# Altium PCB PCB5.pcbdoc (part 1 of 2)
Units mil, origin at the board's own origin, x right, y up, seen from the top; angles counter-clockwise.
Board outline 5683.34 x 2704.79 mil, 4 copper layers (Top Layer, Inner1, Inner2, Bottom Layer); 104 components, 86 nets, 284 pads, 113 vias.
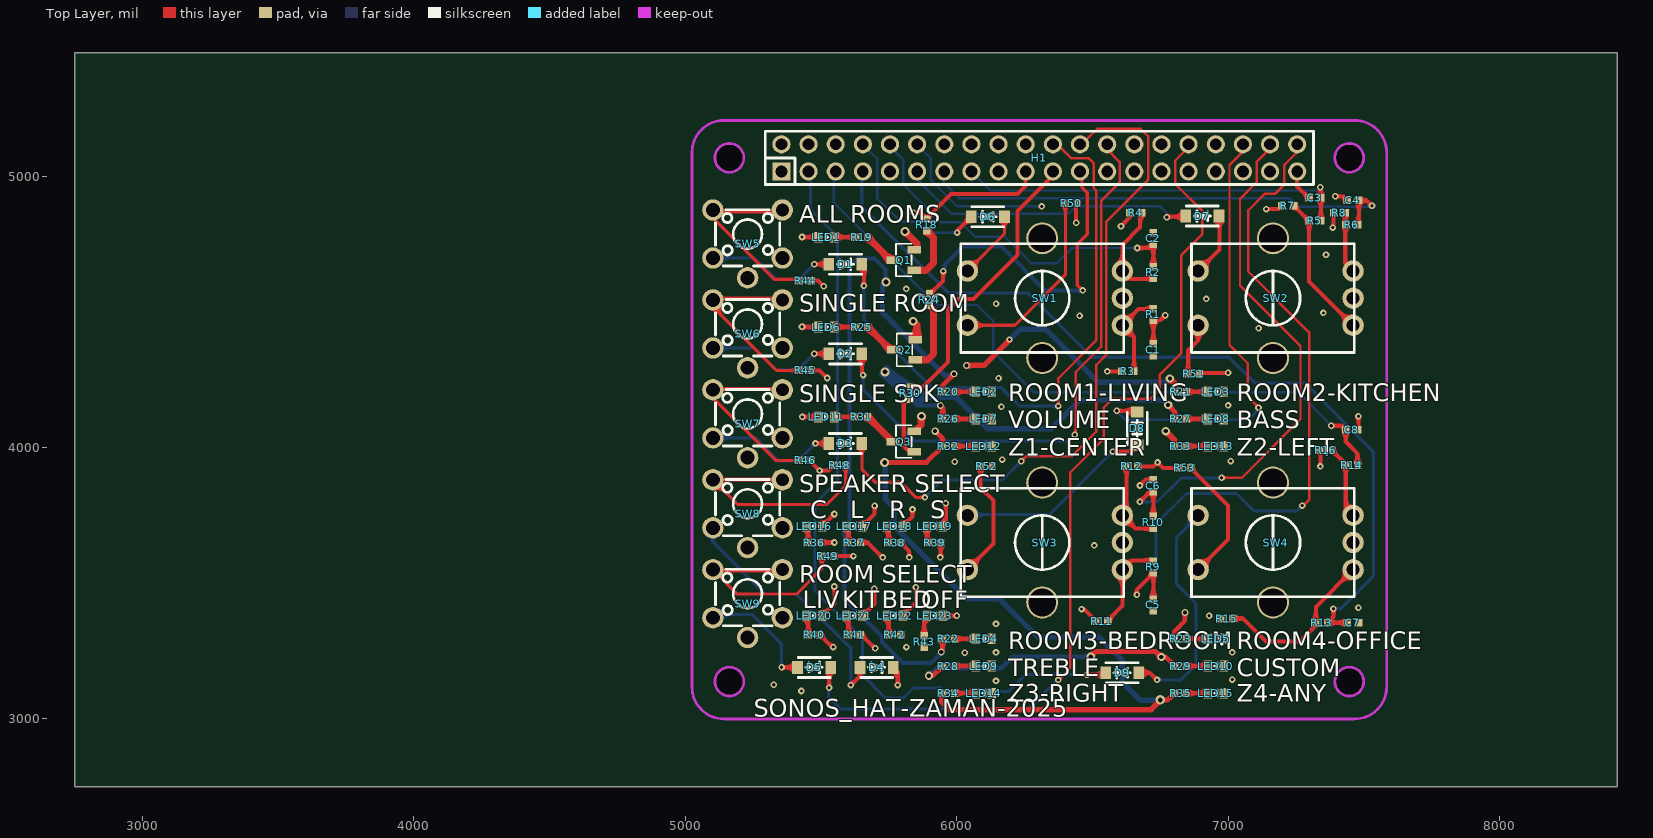
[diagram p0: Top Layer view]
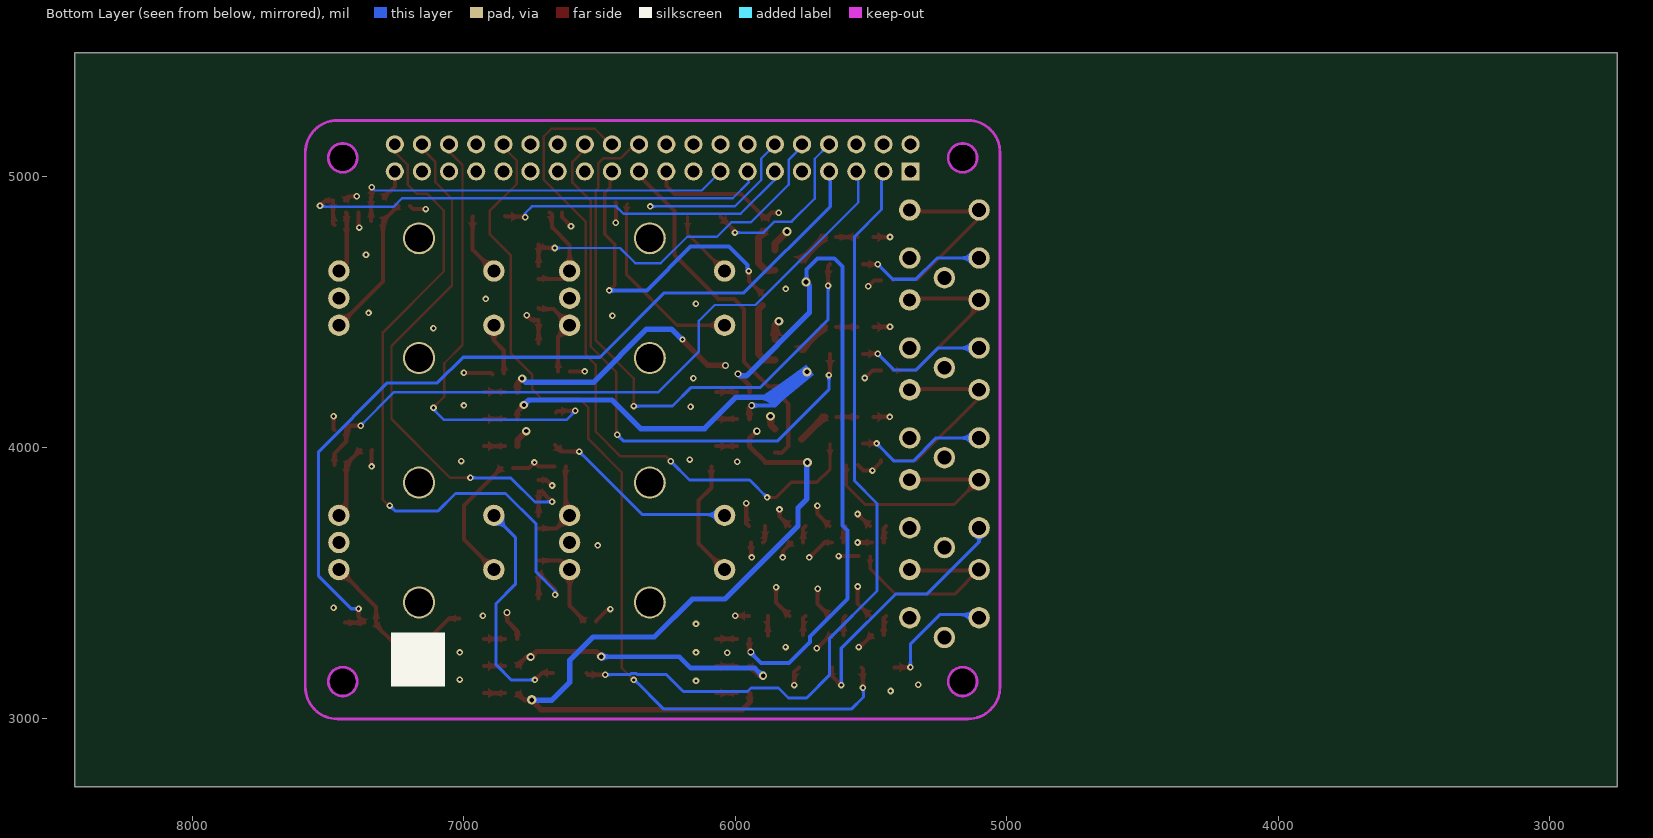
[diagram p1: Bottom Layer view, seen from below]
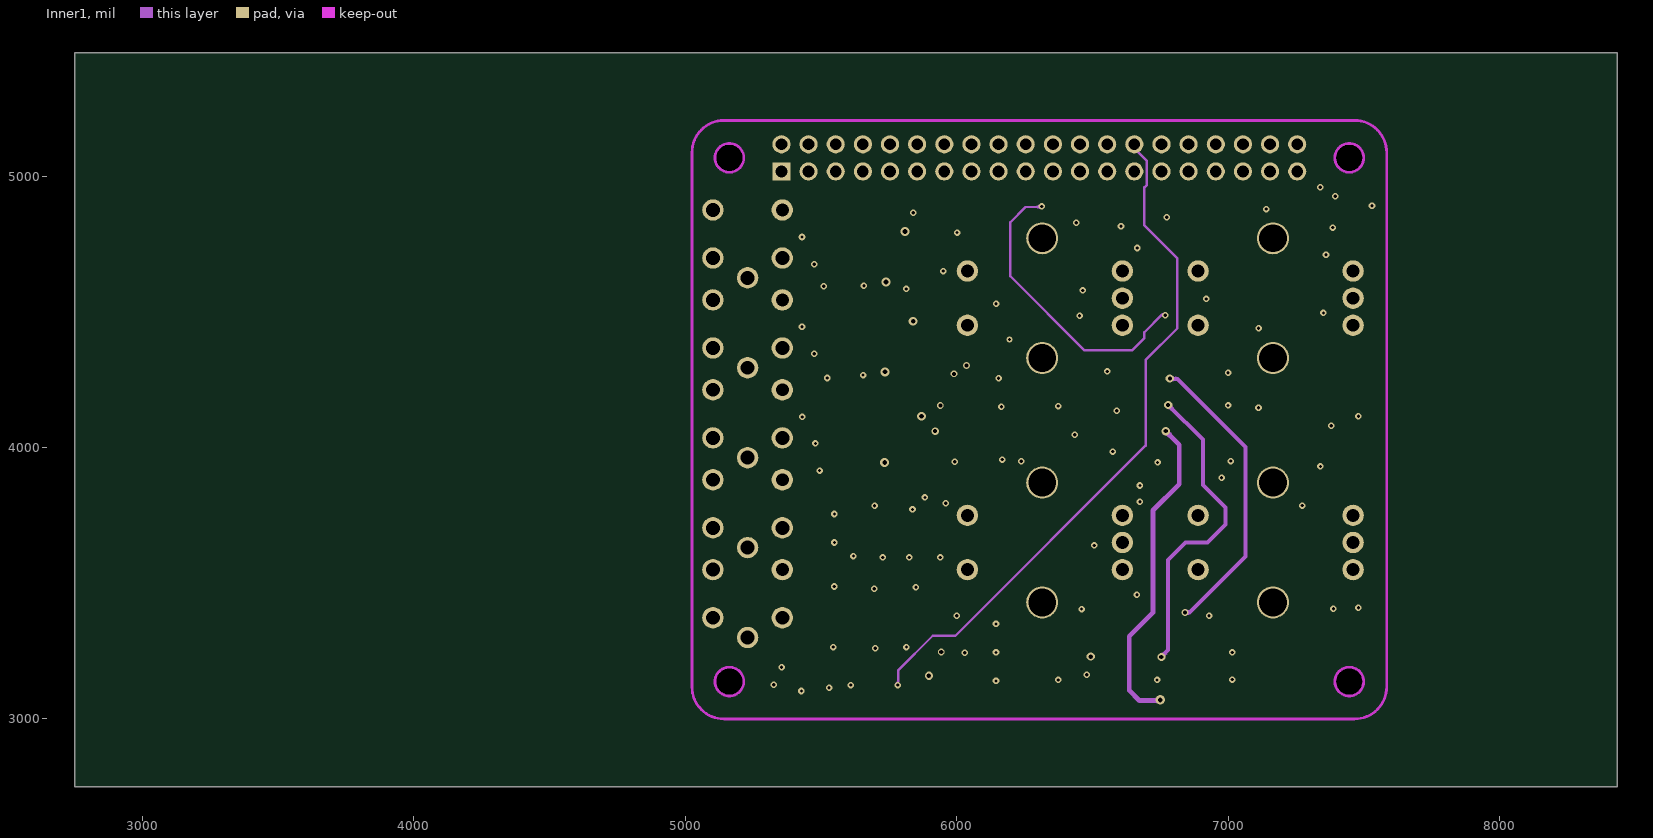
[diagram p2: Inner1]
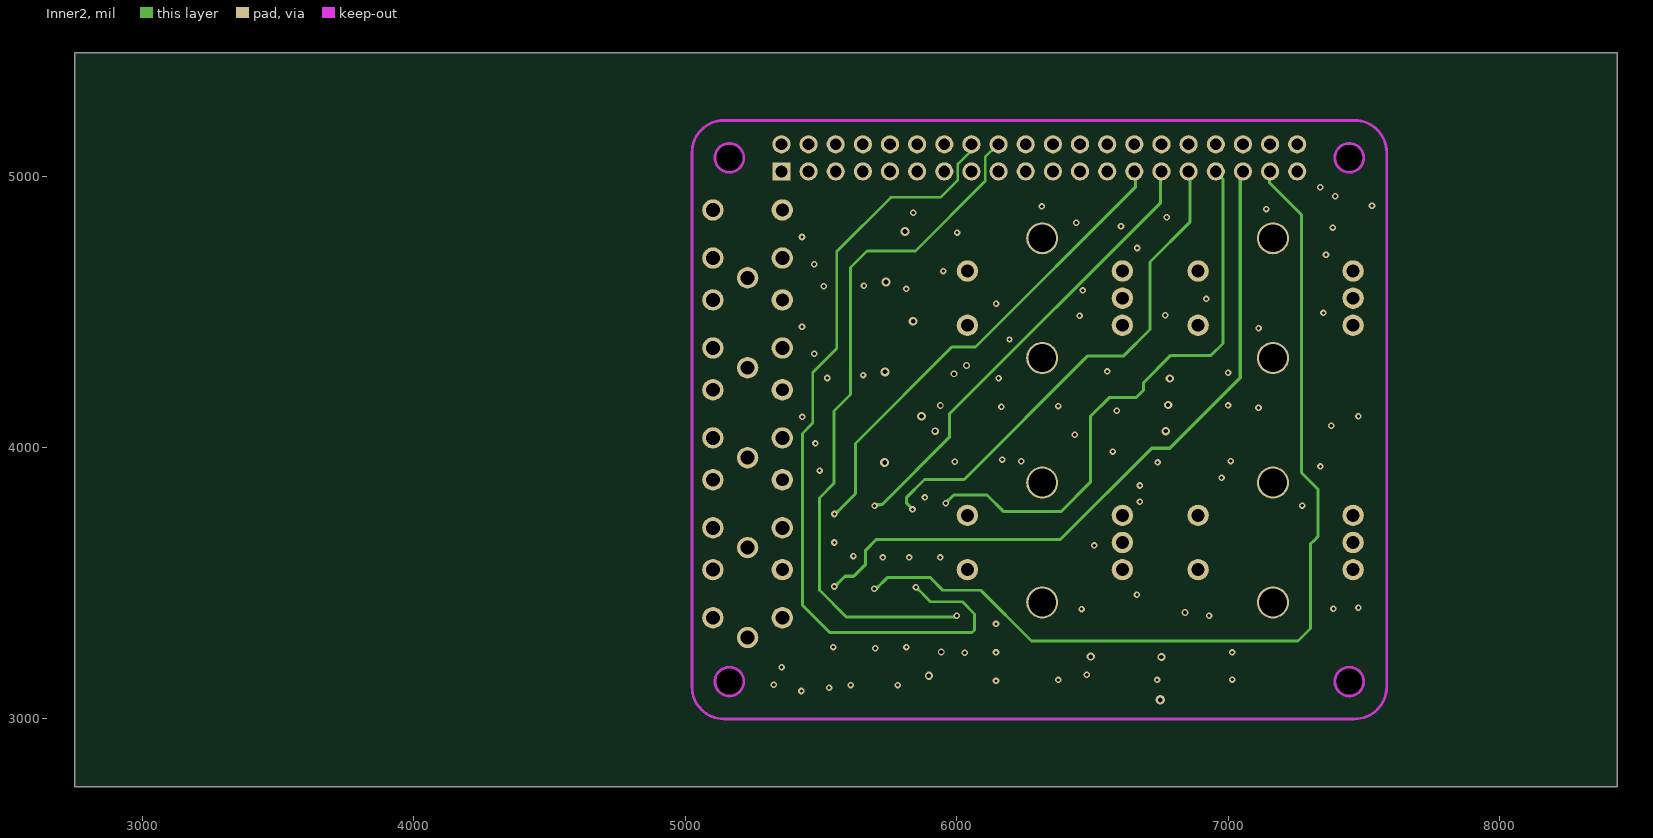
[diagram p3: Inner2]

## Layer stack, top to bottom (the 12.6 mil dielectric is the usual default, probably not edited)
Top Layer: signal copper (thickness not stored)
Dielectric: dielectric 12.6, FR-4, Dk 4.8
Inner1: signal copper (thickness not stored)
Dielectric: dielectric 12.6, FR-4, Dk 4.8
Inner2: signal copper (thickness not stored)
Dielectric: dielectric 12.6, FR-4, Dk 4.8
Bottom Layer: signal copper (thickness not stored)

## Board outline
8433.34,2750 2750,2750 2750,5454.79 8433.34,5454.79
cut-out: 5215.18,3137.86 ccw(c5162.03,3137.86) 5108.88,3137.86 ccw(c5162.03,3137.86)
cut-out: 5215.18,5066.99 ccw(c5162.03,5066.99) 5108.88,5066.99 ccw(c5162.03,5066.99)
cut-out: 7498.65,3137.86 ccw(c7445.5,3137.59) 7392.35,3137.86 ccw(c7445.5,3138.13)
cut-out: 7498.65,5066.99 ccw(c7445.5,5066.72) 7392.35,5066.99 ccw(c7445.5,5067.26)

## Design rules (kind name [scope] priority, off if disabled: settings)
BoardOutlineClearance copperThickness1oz [All] p0: genericclearance=10 ignorepadtopadclearanceinfootprint=FALSE except(0: Arc-SplitContinuation Track-SplitContinuation SMDPad-SplitContinuation THPad-SplitContinuation Via-SplitContinuation Fill-SplitContinuation Poly-SplitContinuation Region-SplitContinuation Text-SplitContinuation; 6: Track-CutoutEdge SMDPad-CutoutEdge THPad-CutoutEdge Via-CutoutEdge Region-CutoutEdge; 11.8: Track-OutlineEdge SMDPad-OutlineEdge THPad-OutlineEdge Via-OutlineEdge Fill-OutlineEdge Region-OutlineEdge Poly-OutlineEdge Text-OutlineEdge Fill-CutoutEdge)
BoardOutlineClearance copperThickness2oz [All] p0: genericclearance=10 ignorepadtopadclearanceinfootprint=FALSE except(0: Arc-SplitContinuation Track-SplitContinuation SMDPad-SplitContinuation THPad-SplitContinuation Via-SplitContinuation Fill-SplitContinuation Poly-SplitContinuation Region-SplitContinuation Text-SplitContinuation; 6: Track-CutoutEdge SMDPad-CutoutEdge THPad-CutoutEdge Via-CutoutEdge Region-CutoutEdge; 11.8: Track-OutlineEdge SMDPad-OutlineEdge THPad-OutlineEdge Via-OutlineEdge Fill-OutlineEdge Region-OutlineEdge Poly-OutlineEdge Text-OutlineEdge Fill-CutoutEdge)
Clearance copperThickness1oz [(InNet('GND') OR InNet('CLK_VOL') OR InNet('DT_VOL') OR InNet('+3.3V') OR InNet('+5V') OR InNet('DT_TREB') OR InNet('CLK_TREB') OR InNet('SW_BASS') OR InNet('DT_BASS') OR InNet('CLK_BASS') OR InNet('A_VOL') OR InNet('B_VOL') OR InNet('A_BASS') OR InNet('B_BASS') OR InNet('A_TREB') OR InNet('B_TREB') OR InNet('SW_TREB') OR InNet('SW_VOL') OR InNet('DT_EXTRA') OR InNet('CLK_EXTRA') OR InNet('SW_EXTRA') OR InNet('A_EXTRA') OR InNet('B_EXTRA') OR InNet('ROOM3_LED') OR InNet('ROOM4_LED') OR InNet('ALL_ROOM_LED') OR InNet('SINGLE_ROOM_LED') OR InNet('SINGLE_SPK_LED') OR InNet('SPK1_LED') OR InNet('SPK2_LED') OR InNet('SPK3_LED') OR InNet('SPK4_LED') OR InNet('ROOM1_LED') OR InNet('ROOM2_LED') OR InNet('$2N567') OR InNet('$2N579') OR InNet('$2N581') OR InNet('$2N585') OR InNet('$2N583') OR InNet('$2N1097') OR InNet('$2N1109') OR InNet('$2N1111') OR InNet('$2N1113') OR InNet('$2N1115') OR InNet('$2N1627') OR InNet('$2N1639') OR InNet('$2N1641') OR InNet('$2N1643') OR InNet('$2N1645') OR InNet('$2N2275') OR InNet('$2N2279') OR InNet('$2N2284') OR InNet('$2N2289') OR InNet('$2N2294') OR InNet('$2N2299') OR InNet('$2N2307') OR InNet('$2N2312') OR InNet('$2N553') OR InNet('$2N557') OR InNet('$2N1083') OR InNet('$2N1087') OR InNet('$2N1613') OR InNet('$2N1617') OR InNet('SW_ALL_ROOM') OR InNet('SW_SINGLE_ROOM') OR InNet('SW_SINGLE_SPK') OR InNet('SW_CHG_SPK') OR InNet('SW_CHG_ROOM') OR InNet('$1N7890') OR InNet('$1N7926') OR InNet('$1N13828') OR InNet('$1N13826') OR InNet('$1N13926') OR InNet('$1N13924') OR InNet('$2N6344') OR InNet('$2N6573') OR InNet('$2N6348') OR InNet('$2N6576') OR InNet('$2N6353') OR InNet('$2N6578') OR InNet('$2N6363') OR InNet('$2N6582') OR InNet('$2N6358') OR InNet('$2N6580') OR InNet('$1N15953') OR InNet('$1N15952'))] p1: gap=7 ignorepadtopadclearanceinfootprint=FALSE except(4: Track-Track; 6: Track-SMDPad SMDPad-SMDPad Track-THPad SMDPad-THPad THPad-THPad Track-Via SMDPad-Via THPad-Via Via-Via SMDPad-Fill THPad-Fill Via-Fill Fill-Fill Track-Region SMDPad-Region THPad-Region Via-Region Region-Region Track-Poly SMDPad-Poly THPad-Poly Via-Poly Fill-Poly Region-Poly Poly-Poly Track-Text SMDPad-Text THPad-Text Via-Text Fill-Text Region-Text Poly-Text Text-Text; 6.9: Track-Hole SMDPad-Hole THPad-Hole Via-Hole Fill-Hole Region-Hole Poly-Hole Text-Hole Sheet-Hole; 11.8: Track-Fill Fill-Region Track-Sheet SMDPad-Sheet THPad-Sheet Via-Sheet Fill-Sheet Region-Sheet Poly-Sheet Text-Sheet)
Clearance copperThickness2oz [All] p1: gap=7 ignorepadtopadclearanceinfootprint=FALSE except(6: Track-SMDPad SMDPad-SMDPad Track-THPad SMDPad-THPad THPad-THPad Track-Via SMDPad-Via THPad-Via Via-Via SMDPad-Fill THPad-Fill Via-Fill Fill-Fill Track-Region SMDPad-Region THPad-Region Via-Region Region-Region Track-Poly SMDPad-Poly THPad-Poly Via-Poly Fill-Poly Region-Poly Poly-Poly Track-Text SMDPad-Text THPad-Text Via-Text Fill-Text Region-Text Poly-Text Text-Text; 6.9: Track-Hole SMDPad-Hole THPad-Hole Via-Hole Fill-Hole Region-Hole Poly-Hole Text-Hole Sheet-Hole; 8: Track-Track; 11.8: Track-Fill Fill-Region Track-Sheet SMDPad-Sheet THPad-Sheet Via-Sheet Fill-Sheet Region-Sheet Poly-Sheet Text-Sheet)
DiffPairsRouting differentialPair [All] p1: maxuncoupledlength=10 minlimit=5.9843 maxlimit=5.9843 mostfreqgap=5.9843 toplayer_minwidth=5 toplayer_prefwidth=10 toplayer_maxwidth=100 bottomlayer_minwidth=5 bottomlayer_prefwidth=10 bottomlayer_maxwidth=100 midlayer1_minwidth=5 midlayer1_prefwidth=10 midlayer1_maxwidth=100 midlayer2_minwidth=5 midlayer2_prefwidth=10 midlayer2_maxwidth=100
PasteMaskExpansion pasteMaskExpansion [All] p1: expansion=0
PlaneConnect innerPlane [All] p1: planeconnectstyle=Relief reliefexpansion=20 reliefentries=4 reliefconductorwidth=10 reliefairgap=10
PolygonConnect copperRegion [All] p1: connectstyle=Direct reliefentries=4 reliefconductorwidth=10 polygonreliefangle="90 Angle" airgapwidth=10
PolygonConnect copperRegion1 [All] p1: connectstyle=Relief reliefentries=4 reliefconductorwidth=10 polygonreliefangle="90 Angle" airgapwidth=10
RoutingVias viaSize [All] p1: viastyle="Through Hole" holewidth=12.0078 minholewidth=11.811 maxholewidth=248.0316 width=24.0158 minwidth=19.685 maxwidth=393.7008
SolderMaskExpansion solderMaskExpansion [All] p1: useseparateexpansions=TRUE expansion=2.0079 expansionbottom=2.0079
Width copperThickness1oz [All] p1: maxlimit=100 minlimit=5 preferedwidth=15
Width copperThickness2oz [All] p1: maxlimit=100 minlimit=8 preferedwidth=10

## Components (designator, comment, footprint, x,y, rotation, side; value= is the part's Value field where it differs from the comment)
C1 "CL05B103KB5NNNC" C0402 6724.24,4360.06 r90 top locked
C2 "CL05B103KB5NNNC" C0402 6724.24,4770.06 r270 top locked
C3 "CL05B103KB5NNNC" C0402 7319.24,4920.06 r0 top
C4 "CL05B103KB5NNNC" C0402 7459.24,4910.06 r0 top
C5 "CL05B103KB5NNNC" C0402 6724.24,3420.06 r90 top
C6 "CL05B103KB5NNNC" C0402 6724.24,3858.69 r270 top
C7 "CL05B103KB5NNNC" C0402 7459.24,3355.06 r180 top
C8 "CL05B103KB5NNNC" C0402 7454.24,4065.06 r180 top
D1 "SM4007PL_C64898" SOD-123F_L2.8-W1.8-LS3.7-RD 5589.24,4675.06 r180 top
D2 "SM4007PL_C64898" SOD-123F_L2.8-W1.8-LS3.7-RD 5589.24,4345.06 r180 top
D3 "SM4007PL_C64898" SOD-123F_L2.8-W1.8-LS3.7-RD 5589.24,4015.06 r180 top
D4 "SM4007PL_C64898" SOD-123F_L2.8-W1.8-LS3.7-RD 5704.24,3190.06 r180 top
D5 "SM4007PL_C64898" SOD-123F_L2.8-W1.8-LS3.7-RD 5474.24,3190.06 r180 top
D6 "SM4007PL_C64898" SOD-123F_L2.8-W1.8-LS3.7-RD 6114.24,4850.06 r0 top
D7 "SM4007PL_C64898" SOD-123F_L2.8-W1.8-LS3.7-RD 6904.69,4852.41 r0 top
D8 "SM4007PL_C64898" SOD-123F_L2.8-W1.8-LS3.7-RD 6664.24,4070.06 r270 top
D9 "SM4007PL_C64898" SOD-123F_L2.8-W1.8-LS3.7-RD 6609.24,3170.06 r0 top
H1 "2.54-2*20P母长PC104" HDR-TH_40P-P2.54-V-F-R2-C20-S2.54-2 6303.77,5066.99 r0 top locked
LED1 "KT-0603R" LED0603-RD 5519.24,4775.06 r180 top
LED2 "KT-0603R" LED0603-RD 6099.24,4205.06 r0 top locked
LED3 "KT-0603R" LED0603-RD 6954.24,4205.06 r0 top locked
LED4 "KT-0603R" LED0603-RD 6099.24,3295.06 r0 top locked
LED5 "KT-0603R" LED0603-RD 6954.24,3295.06 r0 top locked
LED6 "KT-0603R" LED0603-RD 5519.24,4443.86 r180 top
LED7 "KT-0603R" LED0603-RD 6099.24,4105.06 r0 top locked
LED8 "KT-0603R" LED0603-RD 6954.24,4105.06 r0 top locked
LED9 "KT-0603R" LED0603-RD 6099.24,3195.06 r0 top locked
LED10 "KT-0603R" LED0603-RD 6954.24,3195.06 r0 top locked
LED11 "KT-0603R" LED0603-RD 5519.24,4112.56 r180 top
LED12 "KT-0603R" LED0603-RD 6099.24,4005.06 r0 top locked
LED13 "KT-0603R" LED0603-RD 6954.24,4005.06 r0 top locked
LED14 "KT-0603R" LED0603-RD 6099.24,3095.06 r0 top locked
LED15 "KT-0603R" LED0603-RD 6954.24,3095.06 r0 top locked
LED16 "KT-0603R" LED0603-RD 5474.24,3710.06 r0 top
LED17 "KT-0603R" LED0603-RD 5622.57,3710.06 r0 top
LED18 "KT-0603R" LED0603-RD 5770.9,3710.06 r0 top
LED19 "KT-0603R" LED0603-RD 5919.24,3710.06 r0 top
LED20 "KT-0603R" LED0603-RD 5474.24,3380.06 r0 top
LED21 "KT-0603R" LED0603-RD 5622.54,3380.06 r0 top
LED22 "KT-0603R" LED0603-RD 5770.94,3380.06 r0 top
LED23 "KT-0603R" LED0603-RD 5919.24,3380.06 r0 top
Q1 "MMBT2222A 1P" SOT-23-3_L2.9-W1.3-P1.90-LS2.4-BR 5804.24,4690.51 r0 top
Q2 "MMBT2222A 1P" SOT-23-3_L2.9-W1.3-P1.90-LS2.4-BR 5806.84,4360.06 r0 top
Q3 "MMBT2222A 1P" SOT-23-3_L2.9-W1.3-P1.90-LS2.4-BR 5804.24,4021.77 r0 top
R1 "0402WGF1002TCE" C0402 6724.24,4490.06 r90 top locked
R2 "0402WGF1002TCE" C0402 6724.24,4645.06 r90 top locked
R3 "0402WGF1002TCE" C0402 6629.24,4280.06 r0 top locked
R4 "0402WGF1002TCE" C0402 6659.24,4865.06 r0 top locked
R5 "0402WGF1002TCE" C0402 7319.24,4835.06 r180 top
R6 "0402WGF1002TCE" C0402 7454.24,4820.06 r0 top
R7 "0402WGF1002TCE" C0402 7219.24,4890.06 r180 top
R8 "0402WGF1002TCE" C0402 7409.24,4865.06 r180 top
R9 "0402WGF1002TCE" C0402 6724.24,3560.06 r270 top
R10 "0402WGF1002TCE" C0402 6724.24,3725.06 r270 top
R11 "0402WGF1002TCE" C0402 6534.24,3360.06 r0 top
R12 "0402WGF1002TCE" C0402 6644.24,3930.06 r180 top
R13 "0402WGF1002TCE" C0402 7344.24,3355.06 r180 top
R14 "0402WGF1002TCE" C0402 7454.24,3935.06 r0 top
R15 "0402WGF1002TCE" C0402 6994.24,3370.06 r180 top
R16 "0402WGF1002TCE" C0402 7359.24,3990.06 r180 top
R18 "0402WGF1001TCE" C0402 5889.24,4820.06 r270 top
R19 "ERJ2RKF1500X" C0402 5649.24,4775.06 r180 top
R20 "ERJ2RKF1500X" C0402 5969.24,4205.06 r0 top locked
R21 "ERJ2RKF1500X" C0402 6824.24,4205.06 r0 top locked
R22 "ERJ2RKF1500X" C0402 5969.24,3295.06 r0 top locked
R23 "ERJ2RKF1500X" C0402 6824.24,3295.06 r0 top locked
R24 "0402WGF1001TCE" C0402 5899.24,4545.06 r270 top
R25 "ERJ2RKF1500X" C0402 5649.24,4443.86 r180 top
R26 "ERJ2RKF1500X" C0402 5969.24,4105.06 r0 top locked
R27 "ERJ2RKF1500X" C0402 6824.24,4105.06 r0 top locked
R28 "ERJ2RKF1500X" C0402 5969.24,3195.06 r0 top locked
R29 "ERJ2RKF1500X" C0402 6824.24,3195.06 r0 top locked
R30 "0402WGF1001TCE" C0402 5829.24,4200.06 r270 top
R31 "ERJ2RKF1500X" C0402 5647.86,4112.56 r180 top
R32 "ERJ2RKF1500X" C0402 5969.24,4005.06 r0 top locked
R33 "ERJ2RKF1500X" C0402 6824.24,4005.06 r0 top locked
R34 "ERJ2RKF1500X" C0402 5969.24,3095.06 r0 top locked
R35 "ERJ2RKF1500X" C0402 6824.24,3095.06 r0 top locked
R36 "ERJ2RKF1500X" C0402 5474.24,3650.06 r180 top
R37 "ERJ2RKF1500X" C0402 5622.54,3650.06 r180 top
R38 "ERJ2RKF1500X" C0402 5770.94,3650.06 r180 top
R39 "ERJ2RKF1500X" C0402 5919.24,3650.06 r180 top
R40 "ERJ2RKF1500X" C0402 5474.24,3310.06 r180 top
R41 "ERJ2RKF1500X" C0402 5622.54,3310.06 r180 top
R42 "ERJ2RKF1500X" C0402 5770.94,3310.06 r180 top
R43 "ERJ2RKF1500X" C0402 5879.24,3285.06 r90 top
R44 "0402WGF1001TCE" C0402 5441.24,4615.06 r180 top
R45 "0402WGF1001TCE" C0402 5441.24,4283.86 r180 top
R46 "0402WGF1001TCE" C0402 5441.24,3952.56 r180 top
R48 "0402WGF1001TCE" C0402 5569.24,3935.06 r0 top
R49 "0402WGF1001TCE" C0402 5524.24,3600.06 r180 top
R50 "0402WGF1001TCE" C0402 6421.03,4900.38 r0 top
R51 "0402WGF1001TCE" C0402 6871.92,4271.63 r0 top
R52 "0402WGF1001TCE" C0402 6109.24,3930.06 r0 top
R53 "0402WGF1001TCE" C0402 6839.24,3925.06 r180 top
SW1 "PEC12R-4230F-S0024" SW-TH_PEC12R-4230F-S0024 6324.24,4550.06 r90 top locked
SW2 "PEC12R-4230F-S0024" SW-TH_PEC12R-4230F-S0024 7174.24,4550.06 r90 top locked
SW3 "PEC12R-4230F-S0024" SW-TH_PEC12R-4230F-S0024 6324.24,3650.06 r90 top locked
SW4 "PEC12R-4230F-S0024" SW-TH_PEC12R-4230F-S0024 7174.24,3650.06 r90 top locked
SW5 "SKHHQVA010" SW-TH_5P-L6.0-W6.0-P4.50-LS6.5 5229.24,4750.06 r0 top
SW6 "SKHHQVA010" SW-TH_5P-L6.0-W6.0-P4.50-LS6.5 5229.24,4418.81 r0 top
SW7 "SKHHQVA010" SW-TH_5P-L6.0-W6.0-P4.50-LS6.5 5229.24,4087.56 r0 top
SW8 "SKHHQVA010" SW-TH_5P-L6.0-W6.0-P4.50-LS6.5 5229.24,3756.31 r0 top
SW9 "SKHHQVA010" SW-TH_5P-L6.0-W6.0-P4.50-LS6.5 5229.24,3425.06 r0 top

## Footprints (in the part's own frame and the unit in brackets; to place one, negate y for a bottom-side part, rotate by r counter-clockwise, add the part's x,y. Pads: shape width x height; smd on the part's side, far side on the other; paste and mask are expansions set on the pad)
C0402 [mm]
  rect 0.7x0.7 smd: 1(-0.55,0) 2(0.55,0)
HDR-TH_40P-P2.54-V-F-R2-C20-S2.54-2 [mm]
  rect 1.7x1.7 hole 1.1: 1(-24.13,-1.27)
  round 1.7 hole 1.1: 2(-24.13,1.27) 3(-21.59,-1.27) 4(-21.59,1.27) 5(-19.05,-1.27) 6(-19.05,1.27) 7(-16.51,-1.27) 8(-16.51,1.27) 9(-13.97,-1.27) 10(-13.97,1.27) 11(-11.43,-1.27) 12(-11.43,1.27) 13(-8.89,-1.27) 14(-8.89,1.27) 15(-6.35,-1.27) 16(-6.35,1.27) 17(-3.81,-1.27) 18(-3.81,1.27) 19(-1.27,-1.27) 20(-1.27,1.27) 21(1.27,-1.27) 22(1.27,1.27) 23(3.81,-1.27) 24(3.81,1.27) 25(6.35,-1.27) 26(6.35,1.27) 27(8.89,-1.27) 28(8.89,1.27) 29(11.43,-1.27) 30(11.43,1.27) 31(13.97,-1.27) 32(13.97,1.27) 33(16.51,-1.27) 34(16.51,1.27) 35(19.05,-1.27) 36(19.05,1.27) 37(21.59,-1.27) 38(21.59,1.27) 39(24.13,-1.27) 40(24.13,1.27)
  silkscreen extent -25.65,-2.5 25.65,2.5
LED0603-RD [mm]
  rect 0.8x1 smd: 1(-0.75,0) 2(0.75,0)
  silkscreen extent -0.18,-0.32 0.17,0.36
SOD-123F_L2.8-W1.8-LS3.7-RD [mm]
  rect 1x1.2 smd: 1(-1.55,0) 2(1.55,0)
  silkscreen extent -1.52,-0.93 1.49,0.95
SOT-23-3_L2.9-W1.3-P1.90-LS2.4-BR [mm]
  rect 1.25x0.7 smd: 1(1,-0.95) 2(1,0.95) 3(-1,0)
  silkscreen extent -0.73,-1.53 0.73,1.53
SW-TH_5P-L6.0-W6.0-P4.50-LS6.5 [mm]
  round 2 hole 1.3: 1(-3.25,3.175) 3(-3.25,-1.325) 4(3.25,-1.325) 5(0.001,-3.175)
  round 2 hole 1.199: 2(3.25,3.175)
  silkscreen extent -3,-2.07 3,3.2
SW-TH_PEC12R-4230F-S0024 [mm]
  round 2 hole 1.2: 1(-2.54,7.25) 2(2.54,7.25) A(-2.54,-7.25) B(2.54,-7.25) C(0,-7.25)
  round 3 hole 2.6: 6(-5.601,0.25) 7(5.601,0.25)
  silkscreen extent -5.08,-7.37 5.08,7.87

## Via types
v1: diameter 24.02, hole 12.01, Top Layer to Bottom Layer, 86 vias
v2: diameter 25, hole 12, Top Layer to Bottom Layer, 7 vias
v3: diameter 33, hole 18, Top Layer to Bottom Layer, 6 vias
v4: diameter 25, hole 15, Top Layer to Bottom Layer, 5 vias
v5: diameter 30, hole 15, Top Layer to Bottom Layer, 3 vias
v6: diameter 30, hole 16, Top Layer to Bottom Layer, 3 vias
v7: diameter 28, hole 15, Top Layer to Bottom Layer, 1 vias
v8: diameter 35, hole 18, Top Layer to Bottom Layer, 1 vias
v9: diameter 22, hole 12, Top Layer to Bottom Layer, 1 vias

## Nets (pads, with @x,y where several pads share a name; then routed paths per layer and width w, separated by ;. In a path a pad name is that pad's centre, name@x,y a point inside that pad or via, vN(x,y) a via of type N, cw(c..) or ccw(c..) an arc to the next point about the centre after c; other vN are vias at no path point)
$1N7890: R50.1 SW1.1 | length 702.1
  Top Layer w12: SW1.1@6038.79,4450.06 6214.24,4450.06 6399.91,4635.73 6399.91,4894.95 R50.1@6396.48,4898.38
$1N7926: D6.2 SW1.2 | length 256.5
  Top Layer w12: SW1.2@6038.79,4650.06 6175.26,4786.53 D6.2@6175.26,4850.06
$1N13826: D7.2 SW2.2 | length 234.2
  Top Layer w15: SW2.2@6888.79,4650.06 6967.29,4728.56 6967.29,4849.73 D7.2@6965.88,4851.14
$1N13828: R51.1 SW2.1 | length 192.3
  Top Layer w15: R51.1@6850.91,4273.42 6852.37,4274.87 6852.37,4358.2 6888.79,4394.61 SW2.1@6888.79,4450.06
$1N13924: D8.2 SW3.2 | length 728
  Top Layer w15: v1(6574.24,3985.06) 6640.26,3985.06 D8.2@6664.24,4009.04
  Bottom Layer w11: SW3.2@6049.13,3752.83 6342.64,3752.83 v1@6579.23,3989.42
$1N13926: R52.1 SW3.1 | length 438.9
  Top Layer w15: SW3.1@6038.79,3550.06 6134.24,3645.51 6134.24,3805.06 6087.59,3851.72 R52.1@6087.59,3930.06
$1N15952: D9.2 SW4.2 | length 855.2
  Top Layer w15: D9.2@6670.26,3170.06 6711.21,3170.06 v1(6737.51,3143.77)
  Bottom Layer w11: v1(6737.51,3143.77) 6824.91,3143.77 6880.45,3199.31 6880.45,3425.42 6809.69,3496.18 6809.69,3669.32 SW4.2@6888.75,3748.38
$1N15953: R53.1 SW4.1 | length 478
  Top Layer w15: R53.1@6860.89,3925.06 6999.23,3786.72 6999.23,3660.51 SW4.1@6888.79,3550.06
$2N553: Q1.1 R18.2 | length 201.4
  Top Layer w25: Q1.1@5852.86,4652.66 5886.84,4652.66 5914.24,4680.06 5914.24,4773.41 R18.2@5889.24,4798.41
$2N557: Q1.3 R19.1 R20.1 R21.1 R22.1 R23.1 | length 4807.4
  Top Layer w15: v4(5942.59,3246.33) 5947.59,3251.33 R22.1@5947.59,3295.06
  Top Layer w17: R23.1@6802.59,3295.06 6802.59,3323.69 6839.93,3361.03 v4(6839.93,3392.35)
  Top Layer w18: R20.1@5947.59,4205.06 5947.59,4229.05 v4(5989.94,4271.4)
  Top Layer w20: v4(6035.99,4302.31) 6100.82,4302.31 v9@6194.11,4395.6
  Top Layer w22: v5(6784.47,4253.69) 6802.59,4235.57 R21.1@6802.59,4205.06
  Top Layer w25: R19.1@5670.89,4775.06 5670.89,4774.78 Q1.3@5755.61,4690.06
  Inner1 w15: v5(6784.47,4253.69) 6785.49,4252.67 6813.05,4252.67 7063.57,4002.14 7063.57,3599.04 6856.89,3392.35 v4(6839.93,3392.35)
  Bottom Layer w15: v3@5737.02,4607.99 5737.02,4655.93 5696.08,4696.87 5634.88,4696.87 5604.07,4666.06 5604.07,3712.55 5585.93,3694.41 5585.93,3442.74 5724.73,3303.93 5724.73,3282.72 5801.37,3206.08 5904.8,3206.08 v4@5945.13,3246.41
  Bottom Layer w20: v3@5733.31,4603.92 5726.2,4596.81 5726.2,4496.79 5958.9,4264.09 5982.63,4264.09 v4(5989.94,4271.4) ; v9@6196.48,4397.97 6234.43,4435.92 6325.75,4435.92 6521.42,4240.25 6771.02,4240.25 v5(6784.47,4253.69)
  other v3: 5739.24,4610.06
  other v9: 6194.11,4397.97
$2N567: LED1.1 R19.2 | length 78.8
  Top Layer w15: LED1.1@5548.77,4775.07 R19.2@5627.59,4775.06
$2N579: LED2.1 R20.2 | length 76.8
  Top Layer w15: R20.2@5992.87,4205.06 LED2.1@6069.71,4205.06
$2N581: LED3.1 R21.2 | length 76.8
  Top Layer w15: R21.2@6847.87,4205.06 LED3.1@6924.71,4205.06
$2N583: LED4.1 R22.2 | length 76.8
  Top Layer w15: R22.2@5992.87,3295.06 LED4.1@6069.71,3295.06
$2N585: LED5.1 R23.2 | length 76.8
  Top Layer w15: R23.2@6847.87,3295.06 LED5.1@6924.71,3295.06
$2N1083: Q2.1 R24.2 | length 255.2
  Top Layer w25: Q2.1@5852.86,4322.66 5891.84,4322.66 5914.24,4345.06 5914.24,4508.41 R24.2@5899.24,4523.41
$2N1087: Q2.3 R25.1 R26.1 R27.1 R28.1 R29.1 | length 3850.9
  Top Layer w17: v6(5896.8,3159.29) 5911.82,3159.29 R28.1@5947.59,3195.06 ; v6(6753.27,3228.39) 6769.26,3228.39 R29.1@6802.59,3195.06
  Top Layer w18: v4(5939.24,4155.06) 5947.59,4146.72 R26.1@5947.59,4105.06 ; v6@6493.44,3230.58 6510.83,3247.97 6732.2,3247.97 v6@6751.97,3228.21 ; v5(6778.47,4156.39) 6802.59,4132.27 R27.1@6802.59,4105.06
  Top Layer w25: R25.1@5670.89,4443.86 5671.81,4443.86 Q2.3@5755.61,4360.06
  Inner1 w15: v6(6753.27,3228.39) 6778.21,3253.33 6778.21,3586.19 6842.18,3650.16 6923.61,3650.16 6989.23,3715.78 6989.23,3778.24 6905.94,3861.53 6905.94,4028.91 v5(6778.47,4156.39)
  Bottom Layer w15: v3@5734.1,4273.45 5852.69,4154.86 v4@5940.45,4154.86 ; v3@5734.1,4278.06 v3@5734.1,4278.19
  Bottom Layer w18: v6@5901.28,3161.01 5927.36,3187.1 6163.76,3187.1 6205.66,3229 v6@6493.44,3229
  Bottom Layer w20: v3@5738.9,4278.06 5831.4,4185.56 5996.24,4185.56 6112.46,4069.34 6348.45,4069.34 6454,4174.89 6759.97,4174.89 v5(6778.47,4156.39)
  other v3: 5734.73,4278.88
  other v6: 6493.44,3229.79
$2N1097: LED6.1 R25.2 | length 78.8
  Top Layer w15: LED6.1@5548.77,4443.87 R25.2@5627.59,4443.86
$2N1109: LED7.1 R26.2 | length 76.8
  Top Layer w15: R26.2@5992.86,4105.06 LED7.1@6069.71,4105.06
$2N1111: LED8.1 R27.2 | length 76.8
  Top Layer w15: R27.2@6847.87,4105.06 LED8.1@6924.71,4105.06
$2N1113: LED9.1 R28.2 | length 76.8
  Top Layer w15: R28.2@5992.87,3195.06 LED9.1@6069.71,3195.06
$2N1115: LED10.1 R29.2 | length 76.8
  Top Layer w15: R29.2@6847.87,3195.06 LED10.1@6924.71,3195.06
$2N1613: Q3.1 R30.2 | length 247.5
  Top Layer w15: R30.2@5829.24,4178.41 5822.59,4178.41 5804.31,4160.14 5804.31,4005.04 5829.8,3979.54 5839.75,3979.54 5841.29,3981.09 Q3.1@5852.99,3981.09
$2N1617: Q3.3 R31.1 R32.1 R33.1 R34.1 R35.1 | length 4141.2
  Top Layer w17: v8(6749.24,3070.06) 6777.59,3070.06 R35.1@6802.59,3095.06
  Top Layer w18: v3(5734.24,3945.06) 5887.59,3945.06 R32.1@5947.59,4005.06 5947.59,4033.01 v7(5920.26,4060.33)
  Top Layer w20: R34.1@5945.72,3093.89 5945.33,3093.5 5945.33,3061.84 5972.85,3034.31 6715.49,3034.31 v8@6750.56,3069.39
  Top Layer w22: v5(6769.51,4060.06) 6802.59,4026.99 R33.1@6802.59,4005.06
  Top Layer w25: R31.1@5669.51,4112.56 5673.11,4112.56 Q3.3@5755.61,4030.06
  Inner1 w18: v8@6744.66,3068.14 6672.62,3068.14 6635.26,3105.5 6635.26,3304.8 6722.13,3391.67 6722.13,3767.83 6819.37,3865.07 6819.37,4010.2 v5(6769.51,4060.06)
  Bottom Layer w15: v3@5732.97,3948.38 v3@5735.68,3945.67
  Bottom Layer w18: v8@6749.17,3071.58 v8@6749.17,3072
  Bottom Layer w20: v3@5735.78,3945.76 5735.78,3810.3 5768.52,3777.56 5768.52,3711.48 6037.99,3442.01 6157.96,3442.01 6298.03,3301.95 6523.68,3301.95 6609.73,3215.9 6609.73,3135 6675.22,3069.51 v8@6747.09,3069.51
$2N1627: LED11.1 R31.2 | length 77.4
  Top Layer w15: LED11.1@5548.77,4112.57 R31.2@5626.21,4112.56
$2N1639: LED12.1 R32.2 | length 76.8
  Top Layer w15: R32.2@5992.87,4005.06 LED12.1@6069.71,4005.06
$2N1641: LED13.1 R33.2 | length 76.8
  Top Layer w15: R33.2@6847.87,4005.06 LED13.1@6924.71,4005.06
$2N1643: LED14.1 R34.2 | length 76.8
  Top Layer w15: R34.2@5992.87,3095.06 LED14.1@6069.71,3095.06
$2N1645: LED15.1 R35.2 | length 76.8
  Top Layer w15: R35.2@6847.87,3095.06 LED15.1@6924.71,3095.06
$2N2275: LED16.1 R36.2 | length 63.3
  Top Layer w15: LED16.1@5444.71,3710.06 5452.59,3702.18 R36.2@5452.59,3650.06
$2N2279: LED17.1 R37.2 | length 63.2
  Top Layer w15: LED17.1@5593.04,3710.06 5600.89,3702.21 R37.2@5600.89,3650.06
$2N2284: LED18.1 R38.2 | length 63.3
  Top Layer w15: LED18.1@5741.37,3710.06 5749.29,3702.14 R38.2@5749.29,3650.06
$2N2289: LED19.1 R39.2 | length 63.3
  Top Layer w15: LED19.1@5889.71,3710.06 5889.71,3657.94 R39.2@5897.59,3650.06
$2N2294: LED20.1 R40.2 | length 73.3
  Top Layer w15: LED20.1@5444.71,3380.06 5452.59,3372.18 R40.2@5452.59,3310.06
$2N2299: LED21.1 R41.2 | length 73.3
  Top Layer w15: LED21.1@5593.01,3380.06 5600.89,3372.18 R41.2@5600.89,3310.06
$2N2307: LED22.1 R42.2 | length 73.3
  Top Layer w15: LED22.1@5741.41,3380.06 5749.29,3372.18 R42.2@5749.29,3310.06
$2N2312: LED23.1 R43.2 | length 73.5
  Top Layer w15: R43.2@5879.24,3306.72 5879.24,3379.59 LED23.1@5879.71,3380.06
$2N6344: R44.2 SW5.1 SW5.2 | length 696.1
  Top Layer w12: SW5.1@5101.29,4868.87 5101.29,4846.69 5327.91,4620.06 5414.59,4620.06 R44.2@5419.59,4615.06
  Top Layer w15: SW5.1@5099.71,4868.87 5101.29,4868.87 SW5.2@5359.42,4868.87
$2N6348: R45.2 SW6.1 SW6.2 | length 700.5
  Top Layer w12: SW6.1@5101.29,4543.81 5101.29,4518.01 5335.44,4283.86 R45.2@5419.59,4283.86
  Top Layer w15: SW6.1@5101.48,4548.67 5355.86,4548.67 SW6.2@5359.42,4545.12
$2N6353: R46.2 SW7.1 SW7.2 | length 697.8
  Top Layer w12: SW7.1@5101.29,4212.56 5101.29,4184.05 5332.78,3952.56 R46.2@5419.59,3952.56
  Top Layer w15: SW7.1@5096.15,4216.03 5348.75,4216.03 SW7.2@5350.53,4217.81
$2N6358: R49.2 SW9.1 SW9.2 | length 775.5
  Top Layer w12: SW9.1@5103.88,3547.47 5191.29,3460.06 5409.24,3460.06 5502.59,3553.41 R49.2@5502.59,3600.06
  Top Layer w15: SW9.1@5101.48,3547.47 5103.88,3547.47 5351.71,3547.47 SW9.2@5355.27,3551.03
$2N6363: R48.2 SW8.1 SW8.2 | length 887.6
  Top Layer w12: SW8.1@5101.29,3881.31 5192.54,3790.06 5520.89,3790.06 5590.89,3860.06 R48.2@5590.89,3935.06
  Top Layer w15: SW8.1@5101.78,3882.2 SW8.2@5357.94,3882.2
$2N6573: D1.2 SW5.3 | length 482
  Top Layer w15: v1(5474.24,4675.06) D1.2@5528.22,4675.06
  Bottom Layer w12: SW5.3@5101.29,4697.9 5256.4,4697.9 5334.24,4620.06 5419.24,4620.06 v1(5474.24,4675.06)
$2N6576: D2.2 SW6.3 | length 485.6
  Top Layer w15: v1(5474.24,4345.06) D2.2@5528.22,4345.06
  Bottom Layer w12: SW6.3@5101.29,4366.65 5252.65,4366.65 5334.24,4285.06 5414.24,4285.06 v1(5474.24,4345.06)
$2N6578: D3.2 SW7.3 | length 489.2
  Top Layer w15: v1(5479.24,4015.06) D3.2@5528.22,4015.06
  Bottom Layer w12: SW7.3@5101.29,4035.4 5258.9,4035.4 5344.24,3950.06 5414.24,3950.06 v1(5479.24,4015.06)
$2N6580: D5.2 SW9.3 | length 447.5
  Top Layer w15: v1(5354.24,3190.06) D5.2@5413.22,3190.06
  Bottom Layer w12: SW9.3@5101.29,3372.9 5113.45,3385.06 5244.24,3385.06 5354.24,3275.06 v1(5354.24,3190.06)
$2N6582: D4.2 SW8.3 | length 935.9
  Top Layer w15: v1(5609.24,3125.06) 5643.22,3159.04 D4.2@5643.22,3190.06
  Bottom Layer w12: SW8.3@5101.29,3704.15 5101.29,3653.01 5294.24,3460.06 5409.24,3460.06 5609.24,3260.06 v1(5609.24,3125.06)
+3.3V: H1.1 H1.17 R3.1 R4.1 R7.2 R8.2 R11.1 R12.1 R15.2 R16.2 R44.1 R45.1 R46.1 R48.1 R49.1 R50.2 R51.2 R52.2 R53.2 | length 1030
  Top Layer w15: R46.1@5462.89,3952.56 5462.89,3946.41 v1(5494.24,3915.06) 5527.59,3915.06 R48.1@5547.59,3935.06 ; R45.1@5462.89,4283.86 5494.66,4283.86 v2(5522.32,4256.2) ; R44.1@5462.89,4615.06 5488.7,4615.06 v2(5509.83,4593.93) ; R49.1@5545.89,3600.06 v1(5619.24,3600.06) ; v2(6439.69,4827.71) 6439.69,4901.54 R50.2@6440.75,4902.59 ; v1(6459.24,3405.06) 6467.59,3405.06 R11.1@6512.59,3360.06 ; v1(6554.24,4280.06) R3.1@6607.59,4280.06 ; v2(6604.24,4815.06) 6637.59,4848.41 R4.1@6637.59,4865.06 ; R12.1@6665.89,3930.06 6724.24,3930.06 v1(6739.24,3945.06) 6759.24,3925.06 R53.2@6817.59,3925.06 ; R51.2@6893.61,4269.73 6898.94,4275.06 v1(6999.24,4275.06) ; v1(7140.02,4878.47) 7185.99,4878.47 R7.2@7197.59,4890.06 ; R16.2@7337.59,3990.06 7339.24,3988.41 v1(7339.24,3930.06) ; v1(7384.24,4810.06) 7387.59,4813.41 R8.2@7387.59,4865.06
  other v1: 7009.24,3950.06 6999.24,4155.06
+5V: H1.2 H1.4 LED1.2 LED2.2 LED3.2 LED4.2 LED5.2 LED6.2 LED7.2 LED8.2 LED9.2 LED10.2 LED11.2 LED12.2 LED13.2 LED14.2 LED15.2 | length 181.1
  Top Layer w15: v2(5429.24,4445.06) 5430.44,4443.86 LED6.2@5489.71,4443.86 ; v2(5429.24,4775.06) LED1.2@5489.71,4775.06 ; v1(5430.09,4112.56) LED11.2@5489.71,4112.56
  other v1: 5427.56,3103.02 6144.24,3140.06 7014.24,3145.06 6144.24,3245.06 7014.24,3245.06 6144.24,3350.06 6929.24,3380.06 6506.24,3639.43 5991.99,3947.21 6166.79,3955.58 6164.24,4150.06 6153.77,4255.22 7359.8,4709.75
A_BASS: R9.1 R11.2 SW3.A | length 340.8
  Top Layer w15: R11.2@6555.89,3360.06 6555.89,3363.37 6609.69,3417.17 SW3.A@6609.69,3550.06 6643.31,3583.69 R9.1@6724.24,3583.69
A_EXTRA: R13.2 R15.1 SW4.A | length 628.5
  Top Layer w15: R15.1@7015.89,3370.06 7054.24,3370.06 7139.24,3285.06 7262.59,3285.06 R13.2@7322.56,3345.04 ; R13.2@7322.59,3345.04 R13.2@7322.59,3355.06 7322.59,3412.96 SW4.A@7459.69,3550.06
A_TREB: R5.2 R7.1 SW2.A | length 531.6
  Top Layer w15: R7.1@7240.89,4890.06 7242.59,4890.06 R5.2@7297.59,4835.06 7297.59,4612.17 SW2.A@7459.69,4450.06
A_VOL: R1.2 R3.2 SW1.A | length 328.8
  Top Layer w15: R3.2@6652.86,4280.06 6652.86,4406.89 SW1.A@6609.69,4450.06 6669.69,4510.06 6720.62,4510.06 R1.2@6724.24,4513.69
ALL_ROOM_LED: H1.19 R18.1 | length 515.3
  Top Layer w15: v1(5839.24,4865.06) 5865.89,4865.06 R18.1@5889.24,4841.72 ; R18.1@5888.77,4843.03 5978.89,4933.16 6223.46,4933.16 6253.5,4963.2 H1.19@6253.5,5004.31
B_BASS: R10.2 R12.2 SW3.B | length 322.6
  Top Layer w15: R12.2@6622.59,3930.06 6625.63,3927.02 6625.63,3766.01 SW3.B@6609.69,3750.06 6658.31,3701.44 R10.2@6724.24,3701.44
B_EXTRA: R14.1 R16.1 SW4.B | length 272.6
  Top Layer w15: R16.1@7380.89,3990.06 7432.59,3938.37 R14.1@7432.59,3935.06 7432.59,3777.17 SW4.B@7459.69,3750.06
B_TREB: R6.1 R8.1 SW2.B | length 228
  Top Layer w15: R8.1@7432.86,4865.06 7430.62,4862.82 7430.62,4679.14 SW2.B@7459.69,4650.06
B_VOL: R2.1 R4.2 SW1.B | length 371.7
  Top Layer w15: R4.2@6682.86,4865.06 6675.34,4857.54 6675.34,4811.46 6609.69,4745.82 SW1.B@6609.69,4650.06 6638.31,4621.44 R2.1@6724.24,4621.44
CLK_BASS: C5.2 H1.40 R9.2 | length 2650.1
  Top Layer w9: H1.40@7247.83,5116.94 7247.83,5114.57 7255.74,5106.66 7255.74,5090.71 7206.51,5041.49 7206.51,4969.22 7171.3,4934.01 7133.88,4934.01 7073.3,4873.44 7073.3,4648.66 7297.67,4424.29 7297.67,3807.22 7275.27,3784.82 7272.46,3784.82 v1(7272.46,3786.14)
  Top Layer w15: v1(6663.17,3457.13) 6663.17,3477.34 R9.2@6724.24,3538.41 ; C5.2@6724.24,3443.69 R9.2@6724.24,3536.44
  Bottom Layer w11: v1(6663.17,3457.13) 6663.17,3471.48 6732.87,3541.18 6732.87,3717.88 6845.53,3830.54 7030.53,3830.54 7095.76,3765.32 7251.11,3765.32 7271.93,3786.14 v1(7272.46,3786.14)
CLK_EXTRA: C7.2 H1.7 R13.1 | length 3195.2
  Top Layer w15: v1(7387.4,3405.59) 7387.4,3376.57 R13.1@7365.89,3355.06 C7.2@7437.59,3355.06
  Bottom Layer w12: H1.7@5649.38,5036.89 5649.38,4887.47 5967.58,4569.27 6260.77,4569.27 6497.93,4332.12 7002.25,4332.12 7096.59,4237.78 7281.88,4237.78 7534.48,3985.18 7534.48,3526.53 7413.98,3406.03 7390.26,3406.03 7389.82,3405.59 v1(7387.4,3405.59)
CLK_TREB: C3.2 H1.15 R5.1 | length 1445.8
  Top Layer w15: v1@7338.7,4956.85 7338.7,4923.64 C3.2@7342.39,4919.95 ; R5.1@7340.89,4835.06 C3.2@7340.89,4920.06
  Bottom Layer w9: H1.15@6051.02,5018.71 6123.02,4946.7 7326.45,4946.7 v1(7338.57,4958.83)
CLK_VOL: C1.2 H1.12 R1.1 | length 1816.5
  Top Layer w15: C1.2@6724.24,4383.69 R1.1@6724.24,4466.44 ; R1.1@6724.65,4470.18 6750.74,4470.18 v1@6764.97,4484.41
  Inner1 w9: v1@6311.3,4885.88 6253.15,4885.88 6196.51,4829.24 6196.51,4631.46 6470.22,4357.76 6645.73,4357.76 6691.12,4403.15 6691.12,4424.57 6755.9,4489.35 v1@6768.63,4489.35
  Bottom Layer w9: H1.12@5853.53,5114.22 5903.66,5064.09 5903.66,4985.6 6001.37,4887.89 v1(6312.74,4887.89)
  other v1: 6767.81,4487.23
DT_BASS: C6.2 H1.38 R10.1 | length 2009.8
  Top Layer w9: v1@6975.1,3888.77 7049.98,3888.77 7265.81,4104.61 7265.81,4374.1 7043.06,4596.86 7043.06,4915.91 7104.4,4977.25 7104.4,5051.72 7153.91,5101.23 H1.38@7153.91,5108.61
  Top Layer w15: v1(6674.24,3800.06) 6711.21,3837.03 C6.2@6724.24,3837.03 ; R10.1@6724.24,3748.69 C6.2@6724.24,3835.06
  Bottom Layer w11: v1@6674.21,3799.5 6737.64,3799.5 6826.18,3888.04 6973.15,3888.04 v1@6973.26,3888.15
  other v1: 6975.07,3888.74
DT_EXTRA: C8.2 H1.5 R14.2 | length 2572.7
  Top Layer w15: v1(7379.24,4080.06) 7417.59,4080.06 C8.2@7432.59,4065.06 7432.59,4021.72 7475.89,3978.41 R14.2@7475.89,3935.06
  Bottom Layer w9: H1.5@5546.26,5028.64 5546.26,4903.43 5924.66,4525.03 6075.17,4525.03 6133.28,4466.92 6133.28,4353.56 6282.71,4204.14 7256.63,4204.14 v1@7379.38,4081.4
DT_TREB: C4.2 H1.13 R6.2 | length 1804.4
  Top Layer w15: R6.2@7475.89,4820.06 7480.89,4825.06 C4.2@7480.89,4910.06 7509.24,4910.06 v1(7529.24,4890.06)
  Bottom Layer w9: H1.13@5950.61,5017.52 5950.61,4976.41 6008.72,4918.3 7226.64,4918.3 7257.28,4887.66 v1@7528.46,4887.66
DT_VOL: C2.2 H1.10 R2.2 | length 1313.9
  Top Layer w15: v2(6664.46,4734.98) 6711.39,4734.98 C2.2@6724.16,4747.75 ; R2.2@6724.24,4668.69 C2.2@6724.24,4746.44
  Bottom Layer w9: H1.10@5750.26,5112.61 5803.13,5059.74 5803.13,4968.03 5941.61,4829.55 6013.56,4829.55 6066.92,4776.19 6176.66,4776.19 6274.33,4678.52 6367.63,4678.52 6424.08,4734.98 v2(6664.46,4734.98)
GND: C1.1 C2.1 C3.1 C4.1 C5.1 C6.1 C7.1 C8.1 H1.6 H1.9 H1.14 H1.20 H1.25 H1.30 H1.34 H1.39 Q1.2 Q2.2 Q3.2 R36.1 R37.1 R38.1 R39.1 R40.1 R41.1 R42.1 R43.1 SW1.C SW2.C SW3.C SW4.C SW5.5 SW6.5 SW7.5 SW8.5 SW9.5 | length 912.1
  Top Layer w15: R40.1@5495.89,3310.06 5540.89,3265.06 v1(5544.24,3265.06) ; R36.1@5495.89,3650.06 v1(5549.24,3650.06) ; R41.1@5644.19,3310.06 5649.24,3310.06 v1(5699.24,3260.06) ; R37.1@5644.19,3650.06 5671.74,3650.06 v1(5726.74,3595.06) ; R38.1@5792.59,3650.06 5824.24,3618.42 v1(5824.24,3595.06) ; v1(5939.24,3595.06) 5940.89,3596.72 R39.1@5940.89,3650.06 ; v1(6674.24,3860.06) 6694.51,3880.34 C6.1@6724.24,3880.34 ; H1.39@7253.77,5016.99 7253.77,4961.91 C3.1@7295.62,4920.06 ; v1(7394.24,4925.06) 7422.59,4925.06 C4.1@7437.59,4910.06 ; C8.1@7475.89,4065.06 7479.24,4068.41 v1(7479.24,4115.06)
  Top Layer w25: v3(5809.24,4795.06) 5852.86,4751.44 Q1.2@5852.86,4727.46 ; v3(5839.24,4465.06) 5852.86,4451.44 Q2.2@5852.86,4397.46 ; Q3.2@5852.86,4067.46 5869.24,4083.84 v3(5869.24,4115.06)
  other v1: 5325.42,3126.52 6028.91,3244.24 5814.24,3265.06 7479.24,3410.06 7111.55,4439.31 6451.99,4485.16 7350.31,4495.5 6144.44,4529.43 6919.04,4547.22 5813.18,4584.25
ROOM1_LED: H1.35 LED20.2 | length 2746.5
  Top Layer w15: LED20.2@5503.77,3380.07 5548.71,3425.01 v1(5548.71,3487.97)
  Inner2 w12: v1(5548.71,3487.97) 5550.12,3487.97 5587.95,3525.79 5619.65,3525.79 5663.59,3569.74 5663.59,3621.2 5703.47,3661.08 6380.87,3661.08 6717.45,3997.66 6784.88,3997.66 7044.36,4257.15 7044.36,5015.81 H1.35@7056.36,5027.81
ROOM2_LED: H1.37 LED21.2 | length 3634.7
  Top Layer w15: LED21.2@5652.07,3380.07 5696.07,3424.07 v1(5696.07,3480.06)
  Inner2 w11: v1@5700.18,3476.54 5745.24,3521.61 5901.1,3521.61 5948.54,3474.17 6088.36,3474.17 6274.88,3287.65 7257.04,3287.65 7303.01,3333.62 7303.01,3645.48 7315.29,3656.98 ; H1.37@7145.67,5018.88 H1.37@7151.03,5018.88 ; H1.37@7151.03,5021.38 H1.37@7151.03,5018.88 ; 7314.9,3656.59 7315.29,3656.98 ; H1.37@7151.03,5018.88 7151.03,4976.44 7270.01,4857.47 7270.01,3907.04 7329.73,3847.32 7329.73,3671.41 7315.29,3656.98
